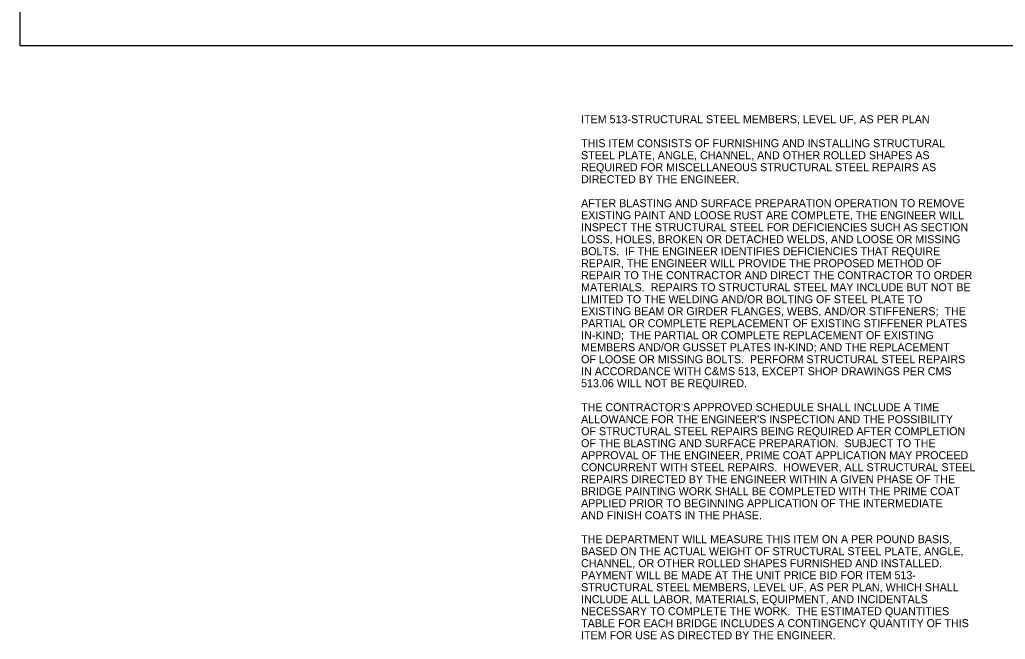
# Model space of a CAD drawing. Extents: x 0 to 34, y -10.4 to 22.
# Drawn here: x 0 to 17.24, y -10.39 to 0.45 of the extents above; entities that cross this region are included whole.
import ezdxf

# ---------------------------------------------------------------- set-up
doc = ezdxf.new("R2010")
doc.units = 0
for name, color, linetype in [('SH_Cut_Line', 7, 'Continuous'), ('SH_Data', 7, 'Continuous'), ('SH_Text', 7, 'Continuous')]:
    doc.layers.add(name, color=color, linetype=linetype)

msp = doc.modelspace()

# ---------------------------------------------------------------- linework, layer by layer
at = {"layer": 'SH_Cut_Line'}
msp.add_lwpolyline([(0, 0), (34, 0), (34, 22), (0, 22)], close=True, dxfattribs=at)
at = {"layer": 'SH_Data'}
msp.add_line((0, 0), (0, 0), dxfattribs=at)

# ---------------------------------------------------------------- texts
at = {"layer": 'SH_Text'}
for s, p in [('ITEM 513-STRUCTURAL STEEL MEMBERS, LEVEL UF, AS PER PLAN', (9.82, -1.358)), ('THIS ITEM CONSISTS OF FURNISHING AND INSTALLING STRUCTURAL ', (9.82, -1.778)), ('STEEL PLATE, ANGLE, CHANNEL, AND OTHER ROLLED SHAPES AS ', (9.82, -1.988)), ('REQUIRED FOR MISCELLANEOUS STRUCTURAL STEEL REPAIRS AS ', (9.82, -2.198)), ('DIRECTED BY THE ENGINEER.', (9.82, -2.408)), ('AFTER BLASTING AND SURFACE PREPARATION OPERATION TO REMOVE ', (9.82, -2.828)), ('EXISTING PAINT AND LOOSE RUST ARE COMPLETE, THE ENGINEER WILL ', (9.82, -3.038)), ('INSPECT THE STRUCTURAL STEEL FOR DEFICIENCIES SUCH AS SECTION ', (9.82, -3.248)), ('LOSS, HOLES, BROKEN OR DETACHED WELDS, AND LOOSE OR MISSING ', (9.82, -3.458)), ('BOLTS.  IF THE ENGINEER IDENTIFIES DEFICIENCIES THAT REQUIRE ', (9.82, -3.668)), ('REPAIR, THE ENGINEER WILL PROVIDE THE PROPOSED METHOD OF ', (9.82, -3.878)), ('REPAIR TO THE CONTRACTOR AND DIRECT THE CONTRACTOR TO ORDER ', (9.82, -4.088)), ('MATERIALS.  REPAIRS TO STRUCTURAL STEEL MAY INCLUDE BUT NOT BE ', (9.82, -4.298)), ('LIMITED TO THE WELDING AND/OR BOLTING OF STEEL PLATE TO ', (9.82, -4.508)), ('EXISTING BEAM OR GIRDER FLANGES, WEBS, AND/OR STIFFENERS;  THE ', (9.82, -4.718)), ('PARTIAL OR COMPLETE REPLACEMENT OF EXISTING STIFFENER PLATES ', (9.82, -4.928)), ('IN-KIND;  THE PARTIAL OR COMPLETE REPLACEMENT OF EXISTING ', (9.82, -5.138)), ('MEMBERS AND/OR GUSSET PLATES IN-KIND; AND THE REPLACEMENT ', (9.82, -5.348)), ('OF LOOSE OR MISSING BOLTS.  PERFORM STRUCTURAL STEEL REPAIRS ', (9.82, -5.558)), ('IN ACCORDANCE WITH C&MS 513, EXCEPT SHOP DRAWINGS PER CMS ', (9.82, -5.768)), ('513.06 WILL NOT BE REQUIRED.', (9.82, -5.978)), ("THE CONTRACTOR'S APPROVED SCHEDULE SHALL INCLUDE A TIME ", (9.82, -6.398)), ("ALLOWANCE FOR THE ENGINEER'S INSPECTION AND THE POSSIBILITY ", (9.82, -6.608)), ('OF STRUCTURAL STEEL REPAIRS BEING REQUIRED AFTER COMPLETION ', (9.82, -6.818)), ('OF THE BLASTING AND SURFACE PREPARATION.  SUBJECT TO THE ', (9.82, -7.028)), ('APPROVAL OF THE ENGINEER, PRIME COAT APPLICATION MAY PROCEED ', (9.82, -7.238)), ('CONCURRENT WITH STEEL REPAIRS.  HOWEVER, ALL STRUCTURAL STEEL ', (9.82, -7.448)), ('REPAIRS DIRECTED BY THE ENGINEER WITHIN A GIVEN PHASE OF THE ', (9.82, -7.658)), ('BRIDGE PAINTING WORK SHALL BE COMPLETED WITH THE PRIME COAT ', (9.82, -7.868)), ('APPLIED PRIOR TO BEGINNING APPLICATION OF THE INTERMEDIATE ', (9.82, -8.078)), ('AND FINISH COATS IN THE PHASE.', (9.82, -8.288)), ('THE DEPARTMENT WILL MEASURE THIS ITEM ON A PER POUND BASIS, ', (9.82, -8.708)), ('BASED ON THE ACTUAL WEIGHT OF STRUCTURAL STEEL PLATE, ANGLE, ', (9.82, -8.918)), ('CHANNEL, OR OTHER ROLLED SHAPES FURNISHED AND INSTALLED.  ', (9.82, -9.128)), ('PAYMENT WILL BE MADE AT THE UNIT PRICE BID FOR ITEM 513-', (9.82, -9.338)), ('STRUCTURAL STEEL MEMBERS, LEVEL UF, AS PER PLAN, WHICH SHALL ', (9.82, -9.548)), ('INCLUDE ALL LABOR, MATERIALS, EQUIPMENT, AND INCIDENTALS ', (9.82, -9.758)), ('NECESSARY TO COMPLETE THE WORK.  THE ESTIMATED QUANTITIES ', (9.82, -9.968)), ('TABLE FOR EACH BRIDGE INCLUDES A CONTINGENCY QUANTITY OF THIS ', (9.82, -10.178)), ('ITEM FOR USE AS DIRECTED BY THE ENGINEER.', (9.82, -10.388))]:
    msp.add_text(s, height=0.14, dxfattribs=at).set_placement(p)

doc.saveas('drawing.dxf')
